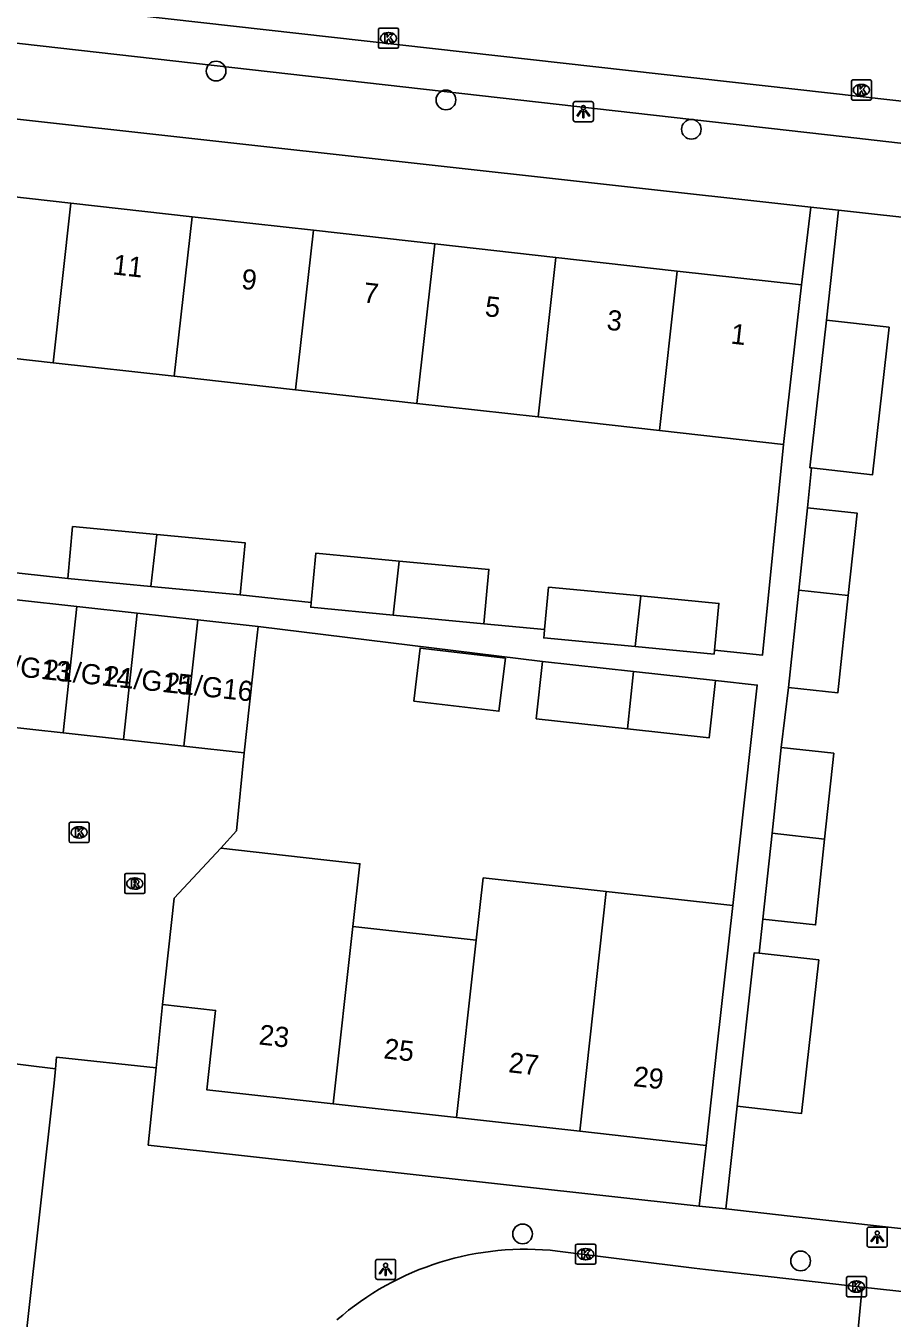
# Model space of a CAD drawing. Extents: x 162082 to 163393, y 388091 to 388632.
# Drawn here: x 162943.3 to 162986.3, y 388384.7 to 388448.7 of the extents above; entities that cross this region are included whole.
import ezdxf

# ---------------------------------------------------------------- set-up
doc = ezdxf.new("R2010")
doc.units = 0
for name, color, linetype in [('IMGEO_Boom', 7, 'Continuous'), ('IMGEO_Kolk', 7, 'Continuous'), ('IMGEO_Lichtpunt', 7, 'Continuous'), ('IMGEO_Muur', 7, 'Continuous'), ('IMGEO_Pand', 7, 'Continuous'), ('IMGEO_Pand_nummerreeks', 7, 'Continuous'), ('IMGEO_Rijbaan_lokaal_open', 7, 'Continuous'), ('IMGEO_Rioolput', 7, 'Continuous'), ('IMGEO_Voetpad_open', 7, 'Continuous')]:
    doc.layers.add(name, color=color, linetype=linetype)

msp = doc.modelspace()

# ---------------------------------------------------------------- linework, layer by layer
at = {"layer": 'IMGEO_Boom'}
for centre in [(162952.784, 388446.497), (162964.19, 388445.064), (162976.367, 388443.609), (162967.992, 388388.834), (162981.789, 388387.494)]:
    msp.add_circle(centre, 0.489, dxfattribs=at)
at = {"layer": 'IMGEO_Kolk'}
for p, q in [((162960.837, 388447.702), (162960.837, 388448.554)), ((162960.912, 388448.628), (162961.764, 388448.628)), ((162961.325, 388448.408), (162961.35, 388448.408)), ((162961.838, 388448.554), (162961.838, 388447.702)), ((162961.764, 388447.628), (162960.912, 388447.628)), ((162961.348, 388447.848), (162961.323, 388447.848)), ((162984.307, 388445.132), (162984.307, 388445.984)), ((162984.382, 388446.058), (162985.234, 388446.058)), ((162984.795, 388445.838), (162984.82, 388445.838)), ((162985.308, 388445.984), (162985.308, 388445.132)), ((162985.234, 388445.058), (162984.382, 388445.058)), ((162984.818, 388445.278), (162984.793, 388445.278)), ((162945.487, 388408.32), (162945.487, 388409.172)), ((162945.562, 388409.246), (162946.414, 388409.246)), ((162945.975, 388409.026), (162946, 388409.026)), ((162946.488, 388409.172), (162946.488, 388408.32)), ((162945.998, 388408.466), (162945.973, 388408.466)), ((162946.414, 388408.246), (162945.562, 388408.246)), ((162970.62, 388387.406), (162970.62, 388388.258)), ((162970.695, 388388.332), (162971.547, 388388.332)), ((162971.108, 388388.112), (162971.133, 388388.112)), ((162971.621, 388388.258), (162971.621, 388387.406)), ((162971.547, 388387.332), (162970.695, 388387.332)), ((162971.131, 388387.552), (162971.106, 388387.552)), ((162984.059, 388385.796), (162984.059, 388386.648)), ((162984.134, 388386.722), (162984.986, 388386.722)), ((162985.06, 388386.648), (162985.06, 388385.796)), ((162984.57, 388385.942), (162984.545, 388385.942)), ((162984.547, 388386.502), (162984.572, 388386.502)), ((162984.986, 388385.722), (162984.134, 388385.722))]:
    msp.add_line(p, q, dxfattribs=at)
for points in [[(162960.837, 388447.702), (162960.837, 388448.554)], [(162960.912, 388448.628), (162961.764, 388448.628)], [(162961.158, 388448.328), (162961.281, 388448.328), (162961.281, 388448.177), (162961.411, 388448.328), (162961.575, 388448.328), (162961.429, 388448.177), (162961.582, 388447.928), (162961.43, 388447.928), (162961.345, 388448.092), (162961.281, 388448.025), (162961.281, 388447.928), (162961.158, 388447.928), (162961.158, 388448.328)], [(162961.838, 388448.554), (162961.838, 388447.702)], [(162961.764, 388447.628), (162960.912, 388447.628)], [(162984.307, 388445.132), (162984.307, 388445.984)], [(162984.382, 388446.058), (162985.234, 388446.058)], [(162984.628, 388445.758), (162984.751, 388445.758), (162984.751, 388445.607), (162984.881, 388445.758), (162985.045, 388445.758), (162984.899, 388445.607), (162985.052, 388445.358), (162984.9, 388445.358), (162984.815, 388445.522), (162984.751, 388445.455), (162984.751, 388445.358), (162984.628, 388445.358), (162984.628, 388445.758)], [(162985.308, 388445.984), (162985.308, 388445.132)], [(162985.234, 388445.058), (162984.382, 388445.058)], [(162945.487, 388408.32), (162945.487, 388409.172)], [(162945.562, 388409.246), (162946.414, 388409.246)], [(162946.488, 388409.172), (162946.488, 388408.32)], [(162945.808, 388408.946), (162945.931, 388408.946), (162945.931, 388408.795), (162946.061, 388408.946), (162946.225, 388408.946), (162946.079, 388408.795), (162946.232, 388408.546), (162946.08, 388408.546), (162945.995, 388408.71), (162945.931, 388408.643), (162945.931, 388408.546), (162945.808, 388408.546), (162945.808, 388408.946)], [(162946.414, 388408.246), (162945.562, 388408.246)], [(162970.62, 388387.406), (162970.62, 388388.258)], [(162970.695, 388388.332), (162971.547, 388388.332)], [(162970.941, 388388.032), (162971.064, 388388.032), (162971.064, 388387.881), (162971.194, 388388.032), (162971.358, 388388.032), (162971.212, 388387.881), (162971.365, 388387.632), (162971.213, 388387.632), (162971.128, 388387.796), (162971.064, 388387.729), (162971.064, 388387.632), (162970.941, 388387.632), (162970.941, 388388.032)], [(162971.621, 388388.258), (162971.621, 388387.406)], [(162971.547, 388387.332), (162970.695, 388387.332)], [(162984.059, 388385.796), (162984.059, 388386.648)], [(162984.134, 388386.722), (162984.986, 388386.722)], [(162985.06, 388386.648), (162985.06, 388385.796)], [(162984.38, 388386.422), (162984.503, 388386.422), (162984.503, 388386.271), (162984.633, 388386.422), (162984.797, 388386.422), (162984.651, 388386.271), (162984.804, 388386.022), (162984.652, 388386.022), (162984.567, 388386.186), (162984.503, 388386.119), (162984.503, 388386.022), (162984.38, 388386.022), (162984.38, 388386.422)], [(162984.986, 388385.722), (162984.134, 388385.722)]]:
    msp.add_lwpolyline(points, dxfattribs=at)
for centre, start, end in [((162960.914, 388448.552), 91.55205, 178.44795), ((162960.914, 388448.552), 91.55205, 178.44795), ((162961.762, 388448.552), 1.55205, 88.44795), ((162961.762, 388448.552), 1.55205, 88.44795), ((162960.914, 388447.704), 181.55205, 268.44795), ((162960.914, 388447.704), 181.55205, 268.44795), ((162961.762, 388447.704), 271.55205, 358.44795), ((162961.762, 388447.704), 271.55205, 358.44795), ((162984.384, 388445.982), 91.55205, 178.44795), ((162984.384, 388445.982), 91.55205, 178.44795), ((162985.232, 388445.982), 1.55205, 88.44795), ((162985.232, 388445.982), 1.55205, 88.44795), ((162984.384, 388445.134), 181.55205, 268.44795), ((162984.384, 388445.134), 181.55205, 268.44795), ((162985.232, 388445.134), 271.55205, 358.44795), ((162985.232, 388445.134), 271.55205, 358.44795), ((162945.564, 388409.17), 91.55205, 178.44795), ((162945.564, 388409.17), 91.55205, 178.44795), ((162946.412, 388409.17), 1.55205, 88.44795), ((162946.412, 388409.17), 1.55205, 88.44795), ((162945.564, 388408.322), 181.55205, 268.44795), ((162945.564, 388408.322), 181.55205, 268.44795), ((162946.412, 388408.322), 271.55205, 358.44795), ((162946.412, 388408.322), 271.55205, 358.44795), ((162970.697, 388388.256), 91.55205, 178.44795), ((162970.697, 388388.256), 91.55205, 178.44795), ((162971.545, 388388.256), 1.55205, 88.44795), ((162971.545, 388388.256), 1.55205, 88.44795), ((162970.697, 388387.408), 181.55205, 268.44795), ((162970.697, 388387.408), 181.55205, 268.44795), ((162971.545, 388387.408), 271.55205, 358.44795), ((162971.545, 388387.408), 271.55205, 358.44795), ((162984.136, 388386.646), 91.55205, 178.44795), ((162984.136, 388386.646), 91.55205, 178.44795), ((162984.984, 388386.646), 1.55205, 88.44795), ((162984.984, 388386.646), 1.55205, 88.44795), ((162984.136, 388385.798), 181.55205, 268.44795), ((162984.136, 388385.798), 181.55205, 268.44795), ((162984.984, 388385.798), 271.55205, 358.44795), ((162984.984, 388385.798), 271.55205, 358.44795)]:
    msp.add_arc(centre, 0.0765, start, end, dxfattribs=at)
for centre, major_axis, ratio, start_param, end_param in [((162961.324, 388448.128), (-0.387, 0.002), 0.722429, 4.712389, 7.853982), ((162961.349, 388448.128), (-0.39, 0.002), 0.717154, 1.570796, 4.712389), ((162984.794, 388445.558), (-0.387, 0.002), 0.722429, 4.712389, 7.853982), ((162984.819, 388445.558), (-0.39, 0.002), 0.717154, 1.570796, 4.712389), ((162945.974, 388408.746), (-0.387, 0.002), 0.722429, 4.712389, 7.853982), ((162945.999, 388408.746), (-0.39, 0.002), 0.717154, 1.570796, 4.712389), ((162971.107, 388387.832), (-0.387, 0.002), 0.722429, 4.712389, 7.853982), ((162971.132, 388387.832), (-0.39, 0.002), 0.717154, 1.570796, 4.712389), ((162984.546, 388386.222), (-0.387, 0.002), 0.722429, 4.712389, 7.853982), ((162984.571, 388386.222), (-0.39, 0.002), 0.717154, 1.570796, 4.712389)]:
    msp.add_ellipse(centre, major_axis=major_axis, ratio=ratio, start_param=start_param, end_param=end_param, dxfattribs=at)
at = {"layer": 'IMGEO_Lichtpunt'}
for p, q in [((162971.413, 388444.982), (162970.605, 388444.982)), ((162971.413, 388444.982), (162970.605, 388444.982)), ((162970.511, 388444.887), (162970.511, 388444.08)), ((162970.511, 388444.887), (162970.511, 388444.08)), ((162971.507, 388444.08), (162971.507, 388444.887)), ((162971.507, 388444.08), (162971.507, 388444.887)), ((162970.605, 388443.986), (162971.413, 388443.986)), ((162970.605, 388443.986), (162971.413, 388443.986)), ((162985.995, 388389.175), (162985.187, 388389.175)), ((162985.995, 388389.175), (162985.187, 388389.175)), ((162985.093, 388389.08), (162985.093, 388388.273)), ((162985.093, 388389.08), (162985.093, 388388.273)), ((162986.089, 388388.273), (162986.089, 388389.08)), ((162986.089, 388388.273), (162986.089, 388389.08)), ((162985.187, 388388.179), (162985.995, 388388.179)), ((162985.187, 388388.179), (162985.995, 388388.179)), ((162960.696, 388387.481), (162960.696, 388386.674)), ((162960.696, 388387.481), (162960.696, 388386.674)), ((162961.598, 388387.576), (162960.79, 388387.576)), ((162961.598, 388387.576), (162960.79, 388387.576)), ((162961.692, 388386.674), (162961.692, 388387.481)), ((162961.692, 388386.674), (162961.692, 388387.481)), ((162960.79, 388386.58), (162961.598, 388386.58)), ((162960.79, 388386.58), (162961.598, 388386.58))]:
    msp.add_line(p, q, dxfattribs=at)
for points in [[(162970.885, 388444.551), (162970.924, 388444.523), (162970.736, 388444.261), (162970.698, 388444.288), (162970.885, 388444.551)], [(162970.987, 388444.503), (162971.034, 388444.503), (162971.034, 388444.181), (162970.987, 388444.181), (162970.987, 388444.503)], [(162971.097, 388444.523), (162971.135, 388444.55), (162971.322, 388444.288), (162971.283, 388444.26), (162971.097, 388444.523)], [(162985.467, 388388.744), (162985.506, 388388.716), (162985.318, 388388.454), (162985.28, 388388.481), (162985.467, 388388.744)], [(162985.569, 388388.696), (162985.616, 388388.696), (162985.616, 388388.374), (162985.569, 388388.374), (162985.569, 388388.696)], [(162985.679, 388388.716), (162985.717, 388388.743), (162985.904, 388388.481), (162985.865, 388388.453), (162985.679, 388388.716)], [(162961.07, 388387.145), (162961.109, 388387.117), (162960.921, 388386.855), (162960.883, 388386.882), (162961.07, 388387.145)], [(162961.172, 388387.097), (162961.219, 388387.097), (162961.219, 388386.775), (162961.172, 388386.775), (162961.172, 388387.097)], [(162961.282, 388387.117), (162961.32, 388387.144), (162961.507, 388386.882), (162961.468, 388386.854), (162961.282, 388387.117)]]:
    msp.add_lwpolyline(points, dxfattribs=at)
for centre in [(162971.01, 388444.685), (162985.592, 388388.878), (162961.195, 388387.279)]:
    msp.add_circle(centre, 0.0994, dxfattribs=at)
for centre, start, end in [((162970.605, 388444.887), 90, 180), ((162970.605, 388444.887), 90, 180), ((162971.413, 388444.887), 0, 90), ((162971.413, 388444.887), 0, 90), ((162970.605, 388444.08), 180, 270), ((162970.605, 388444.08), 180, 270), ((162971.413, 388444.08), 270, 0), ((162971.413, 388444.08), 270, 360), ((162985.187, 388389.08), 90, 180), ((162985.187, 388389.08), 90, 180), ((162985.995, 388389.08), 0, 90), ((162985.995, 388389.08), 0, 90), ((162985.187, 388388.273), 180, 270), ((162985.187, 388388.273), 180, 270), ((162985.995, 388388.273), 270, 0), ((162985.995, 388388.273), 270, 360), ((162960.79, 388387.481), 90, 180), ((162960.79, 388387.481), 90, 180), ((162961.598, 388387.481), 0, 90), ((162961.598, 388387.481), 0, 90), ((162960.79, 388386.674), 180, 270), ((162960.79, 388386.674), 180, 270), ((162961.598, 388386.674), 270, 0), ((162961.598, 388386.674), 270, 360)]:
    msp.add_arc(centre, 0.0946, start, end, dxfattribs=at)
at = {"layer": 'IMGEO_Muur'}
for points in [[(162993.085, 388438.557), (162983.677, 388439.599)], [(162981.271, 388389.719), (162986.148, 388389.172)]]:
    msp.add_lwpolyline(points, dxfattribs=at)
at = {"layer": 'IMGEO_Pand'}
for points in [[(162945.579, 388439.949), (162939.561, 388440.622)], [(162945.579, 388439.949), (162944.692, 388432.037)], [(162951.595, 388439.276), (162945.579, 388439.949)], [(162950.711, 388431.364), (162951.595, 388439.276)], [(162957.613, 388438.603), (162951.595, 388439.276)], [(162956.729, 388430.691), (162957.613, 388438.603)], [(162963.631, 388437.93), (162957.613, 388438.603)], [(162962.746, 388430.018), (162963.631, 388437.93)], [(162969.649, 388437.257), (162963.631, 388437.93)], [(162968.764, 388429.345), (162969.649, 388437.257)], [(162975.666, 388436.584), (162969.649, 388437.257)], [(162975.666, 388436.584), (162974.781, 388428.672)], [(162981.833, 388435.894), (162975.666, 388436.584)], [(162981.833, 388435.894), (162981.277, 388430.925), (162980.948, 388427.982)], [(162982.334, 388426.816), (162982.248, 388426.826), (162983.066, 388434.14)], [(162983.066, 388434.14), (162986.181, 388433.792), (162985.363, 388426.477), (162982.334, 388426.816)], [(162938.677, 388432.71), (162944.692, 388432.037)], [(162944.692, 388432.037), (162950.711, 388431.364)], [(162950.711, 388431.364), (162956.729, 388430.691)], [(162956.729, 388430.691), (162962.746, 388430.018)], [(162962.746, 388430.018), (162968.764, 388429.345)], [(162968.764, 388429.345), (162974.781, 388428.672)], [(162974.781, 388428.672), (162980.948, 388427.982)], [(162981.693, 388420.763), (162982.125, 388424.84)], [(162982.125, 388424.84), (162984.59, 388424.578), (162984.155, 388420.487)], [(162949.835, 388423.516), (162945.664, 388423.911), (162945.42, 388421.33)], [(162949.835, 388423.516), (162949.546, 388420.94)], [(162953.985, 388420.519), (162954.229, 388423.1), (162949.835, 388423.516)], [(162961.872, 388422.204), (162957.736, 388422.596), (162957.504, 388420.146)], [(162961.572, 388419.519), (162961.872, 388422.204)], [(162966.067, 388419.093), (162966.322, 388421.783), (162961.872, 388422.204)], [(162949.546, 388420.94), (162945.42, 388421.33)], [(162953.985, 388420.519), (162949.546, 388420.94)], [(162973.864, 388420.47), (162969.282, 388420.904), (162969.083, 388418.802)], [(162981.183, 388415.937), (162981.693, 388420.763)], [(162981.693, 388420.763), (162984.155, 388420.487)], [(162942.879, 388420.277), (162945.877, 388419.946)], [(162945.877, 388419.946), (162945.187, 388413.687)], [(162945.877, 388419.946), (162948.874, 388419.616)], [(162957.504, 388420.146), (162957.481, 388419.907), (162961.572, 388419.519)], [(162973.864, 388420.47), (162973.583, 388417.961)], [(162977.513, 388417.782), (162977.733, 388420.104), (162973.864, 388420.47)], [(162984.155, 388420.487), (162983.644, 388415.675), (162981.183, 388415.937)], [(162948.184, 388413.357), (162948.874, 388419.616)], [(162948.874, 388419.616), (162951.872, 388419.286)], [(162951.872, 388419.286), (162951.181, 388413.026)], [(162951.872, 388419.286), (162954.869, 388418.955)], [(162966.067, 388419.093), (162961.572, 388419.519)], [(162954.869, 388418.955), (162954.727, 388417.666), (162954.179, 388412.696)], [(162973.583, 388417.961), (162969.044, 388418.391), (162969.06, 388418.564), (162969.083, 388418.802)], [(162962.588, 388415.26), (162962.904, 388417.889), (162967.138, 388417.38), (162966.821, 388414.75), (162962.588, 388415.26)], [(162977.513, 388417.782), (162977.495, 388417.591), (162973.583, 388417.961)], [(162973.191, 388413.883), (162968.669, 388414.379), (162968.98, 388417.223)], [(162968.98, 388417.223), (162973.497, 388416.728)], [(162973.497, 388416.728), (162973.191, 388413.883)], [(162973.497, 388416.728), (162977.565, 388416.282)], [(162977.565, 388416.282), (162977.253, 388413.438), (162973.191, 388413.883)], [(162942.189, 388414.018), (162945.187, 388413.687)], [(162945.187, 388413.687), (162948.184, 388413.357)], [(162948.184, 388413.357), (162951.181, 388413.026)], [(162951.181, 388413.026), (162954.179, 388412.696)], [(162980.373, 388408.703), (162980.824, 388412.949)], [(162980.824, 388412.949), (162983.433, 388412.672), (162982.98, 388408.411)], [(162979.92, 388404.439), (162980.373, 388408.703)], [(162982.98, 388408.411), (162982.529, 388404.162), (162979.92, 388404.439)], [(162982.98, 388408.411), (162980.373, 388408.703)], [(162953.014, 388407.957), (162950.705, 388405.493), (162950.117, 388400.21)], [(162953.014, 388407.957), (162957.984, 388407.404), (162959.921, 388407.189), (162959.575, 388404.08)], [(162965.694, 388403.399), (162966.038, 388406.491), (162972.143, 388405.812)], [(162970.827, 388393.924), (162972.143, 388405.812)], [(162972.143, 388405.812), (162978.418, 388405.114)], [(162978.418, 388405.114), (162977.649, 388398.197), (162977.096, 388393.227)], [(162959.575, 388404.08), (162958.588, 388395.286)], [(162959.575, 388404.08), (162965.694, 388403.399)], [(162964.707, 388394.605), (162965.694, 388403.399)], [(162979.741, 388402.754), (162979.492, 388402.782), (162978.641, 388395.168)], [(162978.641, 388395.168), (162981.84, 388394.81), (162982.692, 388402.424), (162979.741, 388402.754)], [(162958.588, 388395.286), (162952.319, 388395.983), (162952.756, 388399.917), (162950.117, 388400.21)], [(162964.707, 388394.605), (162958.588, 388395.286)], [(162970.827, 388393.924), (162964.707, 388394.605)], [(162977.096, 388393.227), (162970.827, 388393.924)]]:
    msp.add_lwpolyline(points, dxfattribs=at)
at = {"layer": 'IMGEO_Rijbaan_lokaal_open'}
for points in [[(162904.56, 388454.238), (163001.108, 388443.395)], [(162954.179, 388412.696), (162953.801, 388408.831), (162953.014, 388407.957)], [(162950.117, 388400.21), (162949.804, 388397.078)], [(162944.822, 388397.027), (162940.506, 388397.545)], [(162949.804, 388397.078), (162944.865, 388397.605), (162944.822, 388397.027)], [(162984.836, 388386.191), (162980.321, 388386.702), (162977.073, 388387.07), (162976.504, 388387.134), (162969.73, 388387.988)], [(162984.268, 388380.165), (162984.836, 388386.191)], [(162996.782, 388384.817), (162993.964, 388385.201), (162984.836, 388386.191)]]:
    msp.add_lwpolyline(points, dxfattribs=at)
msp.add_arc((162968.137, 388373.838), 14.24, 83.57852, 131.07649, dxfattribs=at)
at = {"layer": 'IMGEO_Rioolput'}
for p, q in [((162948.249, 388405.784), (162948.249, 388406.636)), ((162948.324, 388406.71), (162949.176, 388406.71)), ((162948.737, 388406.49), (162948.762, 388406.49)), ((162949.25, 388406.636), (162949.25, 388405.784)), ((162948.76, 388405.93), (162948.735, 388405.93)), ((162949.176, 388405.71), (162948.324, 388405.71))]:
    msp.add_line(p, q, dxfattribs=at)
for points in [[(162948.249, 388405.784), (162948.249, 388406.636)], [(162948.324, 388406.71), (162949.176, 388406.71)], [(162949.25, 388406.636), (162949.25, 388405.784)], [(162948.838, 388406.408), (162948.586, 388406.41), (162948.586, 388406.01)], [(162948.586, 388406.01), (162948.71, 388406.01), (162948.71, 388406.172), (162948.721, 388406.172)], [(162948.764, 388406.329), (162948.71, 388406.329), (162948.71, 388406.248)], [(162948.71, 388406.248), (162948.762, 388406.248)], [(162948.768, 388406.143), (162948.839, 388406.01), (162948.979, 388406.01), (162948.914, 388406.136)], [(162949.176, 388405.71), (162948.324, 388405.71)]]:
    msp.add_lwpolyline(points, dxfattribs=at)
for centre, radius, start, end in [((162948.326, 388406.634), 0.0765, 91.55205, 178.44795), ((162948.326, 388406.634), 0.0765, 91.55205, 178.44795), ((162949.174, 388406.634), 0.0765, 1.55205, 88.44795), ((162949.174, 388406.634), 0.0765, 1.55205, 88.44795), ((162948.72, 388406.119), 0.0533, 26.02933, 88.69889), ((162948.746, 388406.437), 0.19, 274.7715, 282.96867), ((162948.77, 388406.233), 0.0964, 77.00612, 93.18647), ((162948.784, 388406.29), 0.0378, 276.66336, 79.67722), ((162948.837, 388406.298), 0.109, 350.36119, 89.41601), ((162948.835, 388406.298), 0.112, 277.58423, 350.98172), ((162948.819, 388406.083), 0.108, 29.51342, 73.79051), ((162948.326, 388405.786), 0.0765, 181.55205, 268.44795), ((162948.326, 388405.786), 0.0765, 181.55205, 268.44795), ((162949.174, 388405.786), 0.0765, 271.55205, 358.44795), ((162949.174, 388405.786), 0.0765, 271.55205, 358.44795)]:
    msp.add_arc(centre, radius, start, end, dxfattribs=at)
for centre, major_axis, ratio, start_param, end_param in [((162948.736, 388406.21), (-0.387, 0.002), 0.722429, 4.712389, 7.853982), ((162948.761, 388406.21), (-0.39, 0.002), 0.717154, 1.570796, 4.712389)]:
    msp.add_ellipse(centre, major_axis=major_axis, ratio=ratio, start_param=start_param, end_param=end_param, dxfattribs=at)
at = {"layer": 'IMGEO_Voetpad_open'}
for points in [[(162907.902, 388451.85), (162984.007, 388443.238), (162987.61, 388442.83), (162997.358, 388441.727)], [(162901.761, 388448.679), (162982.293, 388439.752)], [(162982.293, 388439.752), (162981.833, 388435.894)], [(162983.671, 388439.6), (162982.293, 388439.752)], [(162983.671, 388439.6), (162983.066, 388434.14)], [(163004.937, 388437.243), (163000, 388437.79), (162993.085, 388438.557), (162983.671, 388439.6)], [(162980.948, 388427.982), (162979.905, 388417.537), (162977.513, 388417.782)], [(162982.334, 388426.816), (162982.125, 388424.84)], [(162945.42, 388421.33), (162941.935, 388421.722)], [(162957.504, 388420.146), (162953.985, 388420.519)], [(162954.869, 388418.955), (162968.98, 388417.223)], [(162969.083, 388418.802), (162966.067, 388419.093)], [(162977.565, 388416.282), (162979.634, 388416.055), (162978.418, 388405.114)], [(162981.183, 388415.937), (162980.824, 388412.949)], [(162979.92, 388404.439), (162979.741, 388402.754)], [(162944.822, 388397.027), (162944.742, 388396.308), (162939.248, 388347.057)], [(162949.804, 388397.078), (162949.42, 388393.24), (162976.762, 388390.219)], [(162978.641, 388395.168), (162978.071, 388390.074)], [(162977.096, 388393.227), (162976.762, 388390.219)], [(162976.762, 388390.219), (162978.071, 388390.074)], [(162978.071, 388390.074), (162981.271, 388389.719), (162986.148, 388389.172), (162999.276, 388387.7)]]:
    msp.add_lwpolyline(points, dxfattribs=at)

# ---------------------------------------------------------------- texts
at = {"layer": 'IMGEO_Pand_nummerreeks'}
for s, rotation, p in [('11', 353.61861, (162947.619, 388436.421)), ('9', 353.61861, (162954.005, 388435.706)), ('7', 353.61861, (162960.047, 388435.03)), ('5', 353.61861, (162966.089, 388434.354)), ('3', 353.61861, (162972.131, 388433.679)), ('1', 353.61861, (162978.287, 388432.99)), ('21/G13', 353.87364, (162941.171, 388416.67)), ('21/G14', 353.87364, (162944.178, 388416.348)), ('21/G15', 353.87364, (162947.185, 388416.025)), ('21/G16', 353.87364, (162950.192, 388415.702)), ('23', 353.65296, (162954.874, 388398.235)), ('25', 353.65296, (162961.068, 388397.546)), ('27', 353.65296, (162967.262, 388396.857)), ('29', 353.65296, (162973.456, 388396.168))]:
    msp.add_text(s, height=1, rotation=rotation, dxfattribs=at).set_placement(p)

doc.saveas('drawing.dxf')
